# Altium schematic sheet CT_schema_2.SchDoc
size 271 x 273 mm
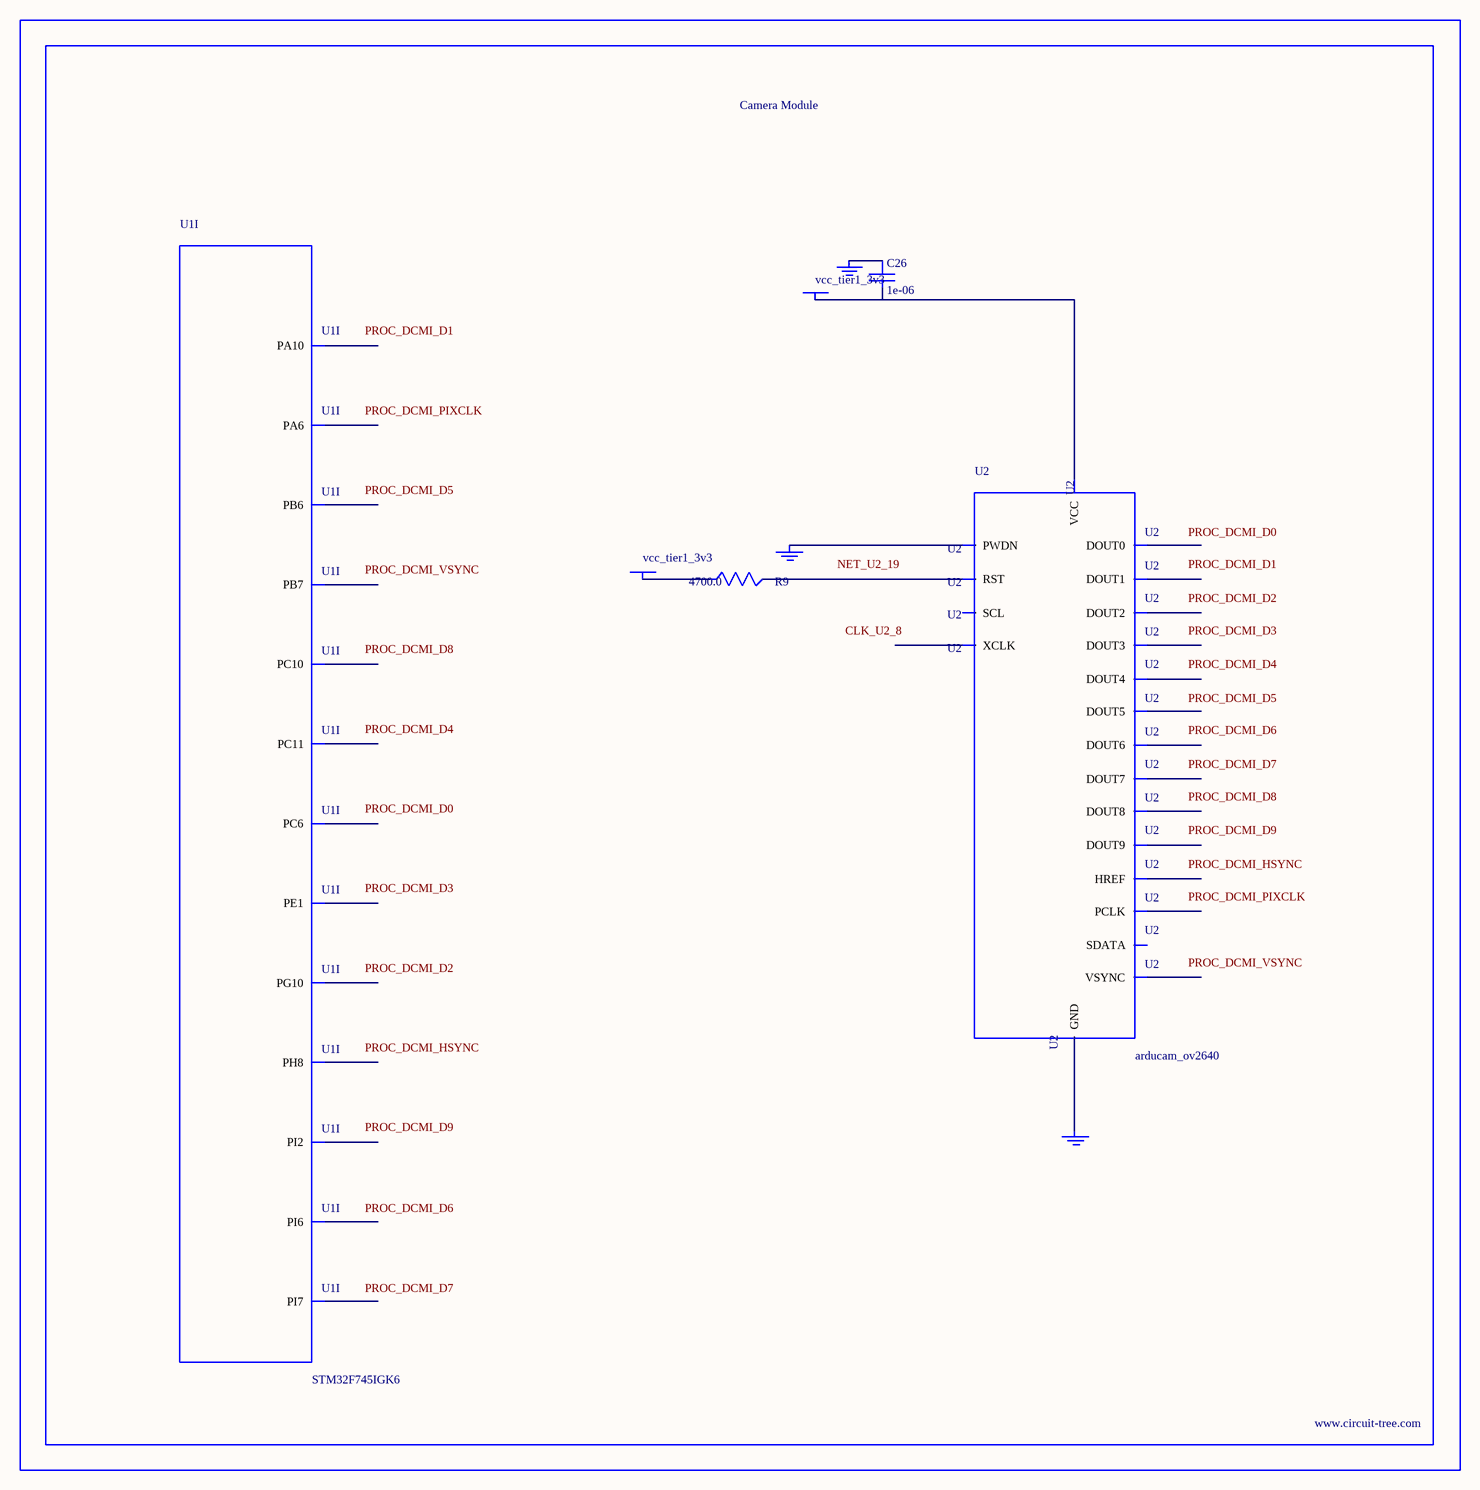
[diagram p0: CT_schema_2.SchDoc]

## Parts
BORDER1  (no value)
C26  1e-06  [C0603]
GND_INSTANCE_1_0  (no value)
GND_INSTANCE_1_1  (no value)
GND_INSTANCE_1_2  (no value)
POWER_INSTANCE_1_0  vcc_tier1_3v3
POWER_INSTANCE_1_1  vcc_tier1_3v3
R9  4700.0  [R0603]
U1  STM32F745IGK6  [UFBGA176_25]  (part I of 16)
U2  arducam_ov2640  [ARDUCAM]

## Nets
NetC26_1: C26.1 GND_INSTANCE_1_0.0(GND)
NetC26_2: C26.2 POWER_INSTANCE_1_0.0(PWR) U2.1(VCC)
NetGND_INSTANCE_1_1_0: GND_INSTANCE_1_1.0(GND) U2.20(PWDN)
NetGND_INSTANCE_1_2_0: GND_INSTANCE_1_2.0(GND) U2.2(GND)
NetPOWER_INSTANCE_1_1_0: POWER_INSTANCE_1_1.0(PWR) R9.1
NetR9_2: R9.2 U2.19(RST)

Not connected (* = marked no-connect by the designer): U1 A3(PE1) B5(PB7) B6(PB6) B10(PG10) B13(PC11) B14(PC10) C2(PI7) C3(PI6) C14(PI2) D15(PA10) H15(PC6) M12(PH8) P3(PA6); U2 3(SCL) 4(SDATA) 5(VSYNC) 6(HREF) 7(PCLK) 8(XCLK) 9(DOUT9) 10(DOUT8) 11(DOUT7) 12(DOUT6) 13(DOUT5) 14(DOUT4) 15(DOUT3) 16(DOUT2) 17(DOUT1) 18(DOUT0)

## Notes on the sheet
- Labels drawn without touching a wire or pin: CLK_U2_8, NET_U2_19, PROC_DCMI_D0, PROC_DCMI_D1, PROC_DCMI_D2, PROC_DCMI_D3, PROC_DCMI_D4, PROC_DCMI_D5, PROC_DCMI_D6, PROC_DCMI_D7, PROC_DCMI_D8, PROC_DCMI_D9, PROC_DCMI_HSYNC, PROC_DCMI_PIXCLK, PROC_DCMI_VSYNC

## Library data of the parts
BORDER1 = BORDER_PAGE1
C26 = C0603C105K3RACTU
GND_INSTANCE_1_0-GND_INSTANCE_1_2 = GND
POWER_INSTANCE_1_0 POWER_INSTANCE_1_1 = PWR
R9 = RC0603JR-074K7L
